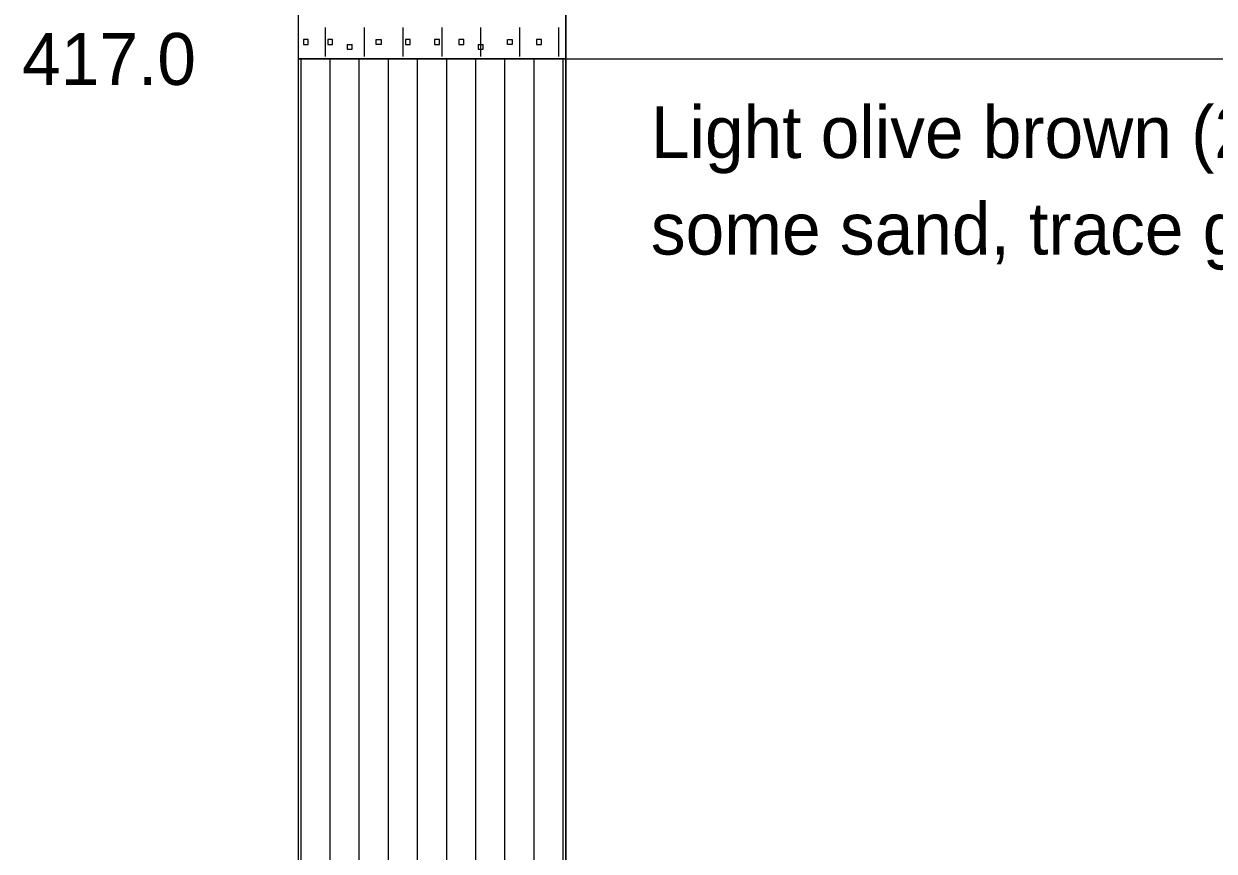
# Model space of a CAD drawing. Extents: x 9422 to 9552, y 6780 to 6860.
# Drawn here: x 9512.85 to 9517.95, y 6828.57 to 6832.12 of the extents above; entities that cross this region are included whole.
import ezdxf

# ---------------------------------------------------------------- set-up
doc = ezdxf.new("R2010")
doc.units = 0
doc.layers.add('7', color=7, linetype='Continuous')
doc.layers.add('8', color=7, linetype='Continuous')

msp = doc.modelspace()

# ---------------------------------------------------------------- linework, layer by layer
at = {"layer": '7'}
for p, q in [((9514.0232, 6839.9684), (9514.0232, 6831.9684)), ((9514.0232, 6839.9684), (9514.0232, 6831.9684)), ((9515.1715, 6831.9684), (9515.1715, 6839.9684)), ((9515.1715, 6831.9684), (9515.1715, 6839.9684)), ((9514.0232, 6831.9684), (9515.1715, 6831.9684)), ((9514.0232, 6831.9684), (9515.1715, 6831.9684)), ((9514.0232, 6831.9684), (9514.0232, 6826.9684)), ((9515.1715, 6831.9684), (9514.0232, 6831.9684)), ((9515.1715, 6826.9684), (9515.1715, 6831.9684)), ((9515.1715, 6831.9684), (9526.1141, 6831.9684))]:
    msp.add_line(p, q, dxfattribs=at)
for points in [[(9514.0232, 6850.4861), (9514.0232, 6821.9406)], [(9515.1715, 6850.4861), (9515.1715, 6821.9406)]]:
    msp.add_lwpolyline(points, dxfattribs=at)
at = {"layer": '8'}
for p, q in [((9514.139, 6832.1038), (9514.139, 6831.9788)), ((9514.3056, 6832.1038), (9514.3056, 6831.9788)), ((9514.4723, 6832.1038), (9514.4723, 6831.9788)), ((9514.639, 6832.1038), (9514.639, 6831.9788)), ((9514.8056, 6832.1038), (9514.8056, 6831.9788)), ((9514.9723, 6832.1038), (9514.9723, 6831.9788)), ((9515.139, 6832.1038), (9515.139, 6831.9788)), ((9514.0661, 6832.0517), (9514.0452, 6832.0517)), ((9514.0452, 6832.0517), (9514.0452, 6832.0309)), ((9514.0661, 6832.0309), (9514.0661, 6832.0517)), ((9514.1702, 6832.0517), (9514.1494, 6832.0517)), ((9514.1494, 6832.0517), (9514.1494, 6832.0309)), ((9514.1702, 6832.0309), (9514.1702, 6832.0517)), ((9514.3577, 6832.0517), (9514.3786, 6832.0517)), ((9514.3577, 6832.0309), (9514.3577, 6832.0517)), ((9514.3786, 6832.0517), (9514.3786, 6832.0309)), ((9514.5036, 6832.0517), (9514.4827, 6832.0517)), ((9514.4827, 6832.0517), (9514.4827, 6832.0309)), ((9514.5036, 6832.0309), (9514.5036, 6832.0517)), ((9514.6286, 6832.0517), (9514.6077, 6832.0517)), ((9514.6077, 6832.0517), (9514.6077, 6832.0309)), ((9514.6286, 6832.0309), (9514.6286, 6832.0517)), ((9514.7327, 6832.0517), (9514.7119, 6832.0517)), ((9514.7119, 6832.0517), (9514.7119, 6832.0309)), ((9514.7327, 6832.0309), (9514.7327, 6832.0517)), ((9514.9202, 6832.0517), (9514.9411, 6832.0517)), ((9514.9202, 6832.0309), (9514.9202, 6832.0517)), ((9514.9411, 6832.0517), (9514.9411, 6832.0309)), ((9515.0661, 6832.0517), (9515.0452, 6832.0517)), ((9515.0452, 6832.0517), (9515.0452, 6832.0309)), ((9515.0661, 6832.0309), (9515.0661, 6832.0517)), ((9515.1715, 6832.0517), (9515.1702, 6832.0517)), ((9515.1702, 6832.0517), (9515.1702, 6832.0309)), ((9514.0452, 6832.0309), (9514.0661, 6832.0309)), ((9514.1494, 6832.0309), (9514.1702, 6832.0309)), ((9514.2327, 6832.0309), (9514.2536, 6832.0309)), ((9514.2327, 6832.0309), (9514.2327, 6832.01)), ((9514.2327, 6832.01), (9514.2536, 6832.01)), ((9514.2536, 6832.01), (9514.2536, 6832.0309)), ((9514.3786, 6832.0309), (9514.3577, 6832.0309)), ((9514.4827, 6832.0309), (9514.5036, 6832.0309)), ((9514.6077, 6832.0309), (9514.6286, 6832.0309)), ((9514.7119, 6832.0309), (9514.7327, 6832.0309)), ((9514.7952, 6832.0309), (9514.8161, 6832.0309)), ((9514.7952, 6832.0309), (9514.7952, 6832.01)), ((9514.7952, 6832.01), (9514.8161, 6832.01)), ((9514.8161, 6832.01), (9514.8161, 6832.0309)), ((9514.9411, 6832.0309), (9514.9202, 6832.0309)), ((9515.0452, 6832.0309), (9515.0661, 6832.0309)), ((9515.1702, 6832.0309), (9515.1715, 6832.0309)), ((9514.0348, 6831.7184), (9514.0348, 6831.9684)), ((9514.1598, 6831.7184), (9514.1598, 6831.9684)), ((9514.2848, 6831.7184), (9514.2848, 6831.9684)), ((9514.4098, 6831.7184), (9514.4098, 6831.9684)), ((9514.5348, 6831.7184), (9514.5348, 6831.9684)), ((9514.6598, 6831.7184), (9514.6598, 6831.9684)), ((9514.7848, 6831.7184), (9514.7848, 6831.9684)), ((9514.9098, 6831.7184), (9514.9098, 6831.9684)), ((9515.0348, 6831.7184), (9515.0348, 6831.9684)), ((9515.1598, 6831.7184), (9515.1598, 6831.9684)), ((9514.0348, 6831.4684), (9514.0348, 6831.7184)), ((9514.1598, 6831.4684), (9514.1598, 6831.7184)), ((9514.2848, 6831.4684), (9514.2848, 6831.7184)), ((9514.4098, 6831.4684), (9514.4098, 6831.7184)), ((9514.5348, 6831.4684), (9514.5348, 6831.7184)), ((9514.6598, 6831.4684), (9514.6598, 6831.7184)), ((9514.7848, 6831.4684), (9514.7848, 6831.7184)), ((9514.9098, 6831.4684), (9514.9098, 6831.7184)), ((9515.0348, 6831.4684), (9515.0348, 6831.7184)), ((9515.1598, 6831.4684), (9515.1598, 6831.7184)), ((9514.0348, 6831.2184), (9514.0348, 6831.4684)), ((9514.1598, 6831.2184), (9514.1598, 6831.4684)), ((9514.2848, 6831.2184), (9514.2848, 6831.4684)), ((9514.4098, 6831.2184), (9514.4098, 6831.4684)), ((9514.5348, 6831.2184), (9514.5348, 6831.4684)), ((9514.6598, 6831.2184), (9514.6598, 6831.4684)), ((9514.7848, 6831.2184), (9514.7848, 6831.4684)), ((9514.9098, 6831.2184), (9514.9098, 6831.4684)), ((9515.0348, 6831.2184), (9515.0348, 6831.4684)), ((9515.1598, 6831.2184), (9515.1598, 6831.4684)), ((9514.0348, 6830.9684), (9514.0348, 6831.2184)), ((9514.1598, 6830.9684), (9514.1598, 6831.2184)), ((9514.2848, 6830.9684), (9514.2848, 6831.2184)), ((9514.4098, 6830.9684), (9514.4098, 6831.2184)), ((9514.5348, 6830.9684), (9514.5348, 6831.2184)), ((9514.6598, 6830.9684), (9514.6598, 6831.2184)), ((9514.7848, 6830.9684), (9514.7848, 6831.2184)), ((9514.9098, 6830.9684), (9514.9098, 6831.2184)), ((9515.0348, 6830.9684), (9515.0348, 6831.2184)), ((9515.1598, 6830.9684), (9515.1598, 6831.2184)), ((9514.0348, 6830.7184), (9514.0348, 6830.9684)), ((9514.1598, 6830.7184), (9514.1598, 6830.9684)), ((9514.2848, 6830.7184), (9514.2848, 6830.9684)), ((9514.4098, 6830.7184), (9514.4098, 6830.9684)), ((9514.5348, 6830.7184), (9514.5348, 6830.9684)), ((9514.6598, 6830.7184), (9514.6598, 6830.9684)), ((9514.7848, 6830.7184), (9514.7848, 6830.9684)), ((9514.9098, 6830.7184), (9514.9098, 6830.9684)), ((9515.0348, 6830.7184), (9515.0348, 6830.9684)), ((9515.1598, 6830.7184), (9515.1598, 6830.9684)), ((9514.0348, 6830.4684), (9514.0348, 6830.7184)), ((9514.1598, 6830.4684), (9514.1598, 6830.7184)), ((9514.2848, 6830.4684), (9514.2848, 6830.7184)), ((9514.4098, 6830.4684), (9514.4098, 6830.7184)), ((9514.5348, 6830.4684), (9514.5348, 6830.7184)), ((9514.6598, 6830.4684), (9514.6598, 6830.7184)), ((9514.7848, 6830.4684), (9514.7848, 6830.7184)), ((9514.9098, 6830.4684), (9514.9098, 6830.7184)), ((9515.0348, 6830.4684), (9515.0348, 6830.7184)), ((9515.1598, 6830.4684), (9515.1598, 6830.7184)), ((9514.0348, 6830.2184), (9514.0348, 6830.4684)), ((9514.1598, 6830.2184), (9514.1598, 6830.4684)), ((9514.2848, 6830.2184), (9514.2848, 6830.4684)), ((9514.4098, 6830.2184), (9514.4098, 6830.4684)), ((9514.5348, 6830.2184), (9514.5348, 6830.4684)), ((9514.6598, 6830.2184), (9514.6598, 6830.4684)), ((9514.7848, 6830.2184), (9514.7848, 6830.4684)), ((9514.9098, 6830.2184), (9514.9098, 6830.4684)), ((9515.0348, 6830.2184), (9515.0348, 6830.4684)), ((9515.1598, 6830.2184), (9515.1598, 6830.4684)), ((9514.0348, 6829.9684), (9514.0348, 6830.2184)), ((9514.1598, 6829.9684), (9514.1598, 6830.2184)), ((9514.2848, 6829.9684), (9514.2848, 6830.2184)), ((9514.4098, 6829.9684), (9514.4098, 6830.2184)), ((9514.5348, 6829.9684), (9514.5348, 6830.2184)), ((9514.6598, 6829.9684), (9514.6598, 6830.2184)), ((9514.7848, 6829.9684), (9514.7848, 6830.2184)), ((9514.9098, 6829.9684), (9514.9098, 6830.2184)), ((9515.0348, 6829.9684), (9515.0348, 6830.2184)), ((9515.1598, 6829.9684), (9515.1598, 6830.2184)), ((9514.0348, 6829.7184), (9514.0348, 6829.9684)), ((9514.1598, 6829.7184), (9514.1598, 6829.9684)), ((9514.2848, 6829.7184), (9514.2848, 6829.9684)), ((9514.4098, 6829.7184), (9514.4098, 6829.9684)), ((9514.5348, 6829.7184), (9514.5348, 6829.9684)), ((9514.6598, 6829.7184), (9514.6598, 6829.9684)), ((9514.7848, 6829.7184), (9514.7848, 6829.9684)), ((9514.9098, 6829.7184), (9514.9098, 6829.9684)), ((9515.0348, 6829.7184), (9515.0348, 6829.9684)), ((9515.1598, 6829.7184), (9515.1598, 6829.9684)), ((9514.0348, 6829.4684), (9514.0348, 6829.7184)), ((9514.1598, 6829.4684), (9514.1598, 6829.7184)), ((9514.2848, 6829.4684), (9514.2848, 6829.7184)), ((9514.4098, 6829.4684), (9514.4098, 6829.7184)), ((9514.5348, 6829.4684), (9514.5348, 6829.7184)), ((9514.6598, 6829.4684), (9514.6598, 6829.7184)), ((9514.7848, 6829.4684), (9514.7848, 6829.7184)), ((9514.9098, 6829.4684), (9514.9098, 6829.7184)), ((9515.0348, 6829.4684), (9515.0348, 6829.7184)), ((9515.1598, 6829.4684), (9515.1598, 6829.7184)), ((9514.0348, 6829.2184), (9514.0348, 6829.4684)), ((9514.1598, 6829.2184), (9514.1598, 6829.4684)), ((9514.2848, 6829.2184), (9514.2848, 6829.4684)), ((9514.4098, 6829.2184), (9514.4098, 6829.4684)), ((9514.5348, 6829.2184), (9514.5348, 6829.4684)), ((9514.6598, 6829.2184), (9514.6598, 6829.4684)), ((9514.7848, 6829.2184), (9514.7848, 6829.4684)), ((9514.9098, 6829.2184), (9514.9098, 6829.4684)), ((9515.0348, 6829.2184), (9515.0348, 6829.4684)), ((9515.1598, 6829.2184), (9515.1598, 6829.4684)), ((9514.0348, 6828.9684), (9514.0348, 6829.2184)), ((9514.1598, 6828.9684), (9514.1598, 6829.2184)), ((9514.2848, 6828.9684), (9514.2848, 6829.2184)), ((9514.4098, 6828.9684), (9514.4098, 6829.2184)), ((9514.5348, 6828.9684), (9514.5348, 6829.2184)), ((9514.6598, 6828.9684), (9514.6598, 6829.2184)), ((9514.7848, 6828.9684), (9514.7848, 6829.2184)), ((9514.9098, 6828.9684), (9514.9098, 6829.2184)), ((9515.0348, 6828.9684), (9515.0348, 6829.2184)), ((9515.1598, 6828.9684), (9515.1598, 6829.2184)), ((9514.0348, 6828.7184), (9514.0348, 6828.9684)), ((9514.1598, 6828.7184), (9514.1598, 6828.9684)), ((9514.2848, 6828.7184), (9514.2848, 6828.9684)), ((9514.4098, 6828.7184), (9514.4098, 6828.9684)), ((9514.5348, 6828.7184), (9514.5348, 6828.9684)), ((9514.6598, 6828.7184), (9514.6598, 6828.9684)), ((9514.7848, 6828.7184), (9514.7848, 6828.9684)), ((9514.9098, 6828.7184), (9514.9098, 6828.9684)), ((9515.0348, 6828.7184), (9515.0348, 6828.9684)), ((9515.1598, 6828.7184), (9515.1598, 6828.9684)), ((9514.0348, 6828.4684), (9514.0348, 6828.7184)), ((9514.1598, 6828.4684), (9514.1598, 6828.7184)), ((9514.2848, 6828.4684), (9514.2848, 6828.7184)), ((9514.4098, 6828.4684), (9514.4098, 6828.7184)), ((9514.5348, 6828.4684), (9514.5348, 6828.7184)), ((9514.6598, 6828.4684), (9514.6598, 6828.7184)), ((9514.7848, 6828.4684), (9514.7848, 6828.7184)), ((9514.9098, 6828.4684), (9514.9098, 6828.7184)), ((9515.0348, 6828.4684), (9515.0348, 6828.7184)), ((9515.1598, 6828.4684), (9515.1598, 6828.7184))]:
    msp.add_line(p, q, dxfattribs=at)

# ---------------------------------------------------------------- texts
at = {"layer": '7'}
for s, p in [('417.0', (9512.8384, 6831.857)), ('Light olive brown (2.5Y 5/6), wet, very stiff, SILT,', (9515.536, 6831.543)), ('some sand, trace gravel, non-plastic (Alluvium)', (9515.536, 6831.1288))]:
    msp.add_text(s, height=0.2228, dxfattribs=at).set_placement(p)

doc.saveas('drawing.dxf')
